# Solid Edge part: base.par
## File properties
Title: Base
Author: Robert a Rhodes jr
Template: Normal.par
Last saved by: Rajat Kamboj
Revision: 28
Application: Solid Edge
Accuracy: 0.99
Material: aluminum
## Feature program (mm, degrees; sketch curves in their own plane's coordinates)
sketch for "unnamed Protrusion 1" plane through (0, 0, 0) normal (0, 0, 1) x-axis (1, 0, 0)
  line (-85, 25) -> (-85, -25)
  arc centre (-80, -25) radius 5 from (-85, -25) to (-80, -30) ccw
  line (-80, -30) -> (80, -30)
  arc centre (80, -25) radius 5 from (85, -25) to (80, -30) cw
  line (85, -25) -> (85, 25)
  arc centre (80, 25) radius 5 from (80, 30) to (85, 25) cw
  line (80, 30) -> (-80, 30)
  arc centre (-80, 25) radius 5 from (-85, 25) to (-80, 30) cw
extrude "unnamed Protrusion 1" add finite 20 along +normal
sketch for "ExtrudedProtrusion_2" plane through (5, -12, 10) normal (0, -1, 0) x-axis (1, 0, 0)
  line (-50, 10) -> (-50, 50)
  arc centre (15, 50) radius 65 from (-50, 50) to (-20, 104.7723) cw
  line (-20, 104.7723) -> (-20, 144)
  arc centre (-17, 144) radius 3 from (-20, 144) to (-17, 147) cw
  line (-17, 147) -> (37, 147)
  arc centre (37, 144) radius 3 from (37, 147) to (40, 144) cw
  line (40, 144) -> (40, 75)
  line (40, 75) -> (-12, 75)
  line (-12, 28.959) -> (-12, 75)
  line (10, 10) -> (-12, 28.959)
  line (28, 35) -> (10, 10)
  line (40, 35) -> (28, 35)
  line (40, 35) -> (40, 10)
extrude "ExtrudedProtrusion_2" add  Plane_Distance = 18 mm
sketch for "unnamed Cutout 1" plane through (5, -12, 88.5) normal (0, -1, 0) x-axis (1, 0, 0)
  line (-20, -68.5) -> (-20, 4.7281)
  arc centre (-25, 4.7281) radius 5 from (-28.8, 7.9777) to (-20, 4.7281) cw
  arc centre (13, -27.7681) radius 55 from (-42, -27.7681) to (-28.8, 7.9777) cw
  line (-42, -68.5) -> (-42, -27.7681)
  line (-42, -68.5) -> (-20, -68.5)
extrude "unnamed Cutout 1" cut finite 10 along -normal
sketch for "ExtrudedCutout_2" plane through (5, 0, 0) normal (0, 0, -1) x-axis (1, 0, 0)
  line (-10, 1) -> (-10, -19)
  line (-10, -19) -> (30, -19)
  line (30, -19) -> (30, 1)
  line (30, 1) -> (-10, 1)
  dimension (linear) = 10
extrude "ExtrudedCutout_2" cut finite 147 along -normal
sketch for "ExtrudedProtrusion_3" plane through (25, 9, 157) normal (0, 0, 1) x-axis (1, 0, 0)
  circle centre (-10, 0) radius 15
  dimension (linear) = 10
extrude "ExtrudedProtrusion_3" add finite 18 along +normal
sketch for "Hole_1" plane through (25, 9, 175) normal (0, 0, 1) x-axis (1, 0, 0)
  hole centre (-10, 0) bore radius 10
hole "Hole_1" diameter 20 finite
sketch for "Hole_2" plane through (45, 9, 119.9119) normal (1, 0, 0) x-axis (0, 1, 0)
  hole centre (1, 20.0881) bore radius 4
  dimension (linear) = 1
hole "Hole_2" diameter 8 through
mirror "unnamed Mirror 1" of "unnamed Cutout 1" about plane through (5, 9, 88.7059) normal (0, -1, 0)
extrude "unnamed Cutout 2" cut finite 10
fillet "Round_1" radius 3
sketch for "Hole_3" plane through (0, 0, 20) normal (0, 0, 1) x-axis (1, 0, 0)
  hole centre (70, 0) bore radius 6.5
hole "Hole_3" diameter 13 through
sketch for "unnamed Hole 1" plane through (0, 0, 20) normal (0, 0, 1) x-axis (1, 0, 0)
  hole centre (-70, 0) bore radius 6.5
  dimension (linear) = 70
  dimension (linear) = 70
hole "unnamed Hole 1" through
pattern "unnamed Pattern 1" of "Hole_3", "unnamed Hole 1"
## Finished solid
Body 1: solid body, 61 faces, 164 edges, 100 vertices.
  Faces by surface: plane 37, cylinder 23, torus 1
  Edges by curve: line 114, circle 50
Bounding box of the edges (mm; curved faces can reach further): 170.000 x 60.000 x 175.000, from (-85, -30, 0) to (85, 30, 175).
Cylindrical faces by radius (mm): R3 x8, R4 x2, R5 x6, R6.5 x2, R10 x1, R15 x1, R55 x2, R65 x1
Toroidal faces (ring radius, tube radius in mm): R18 r3 x1
Planar faces by outward normal: +x 8, +y 4, +z 5, -x 7, -y 6, -z 4, oblique 3
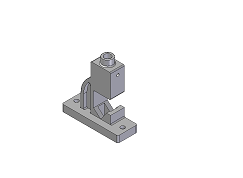
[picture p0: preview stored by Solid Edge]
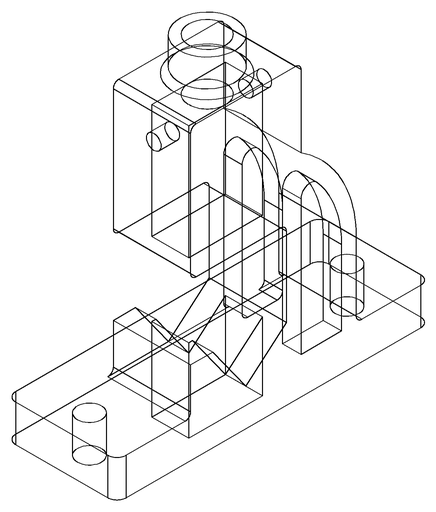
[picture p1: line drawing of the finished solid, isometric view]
